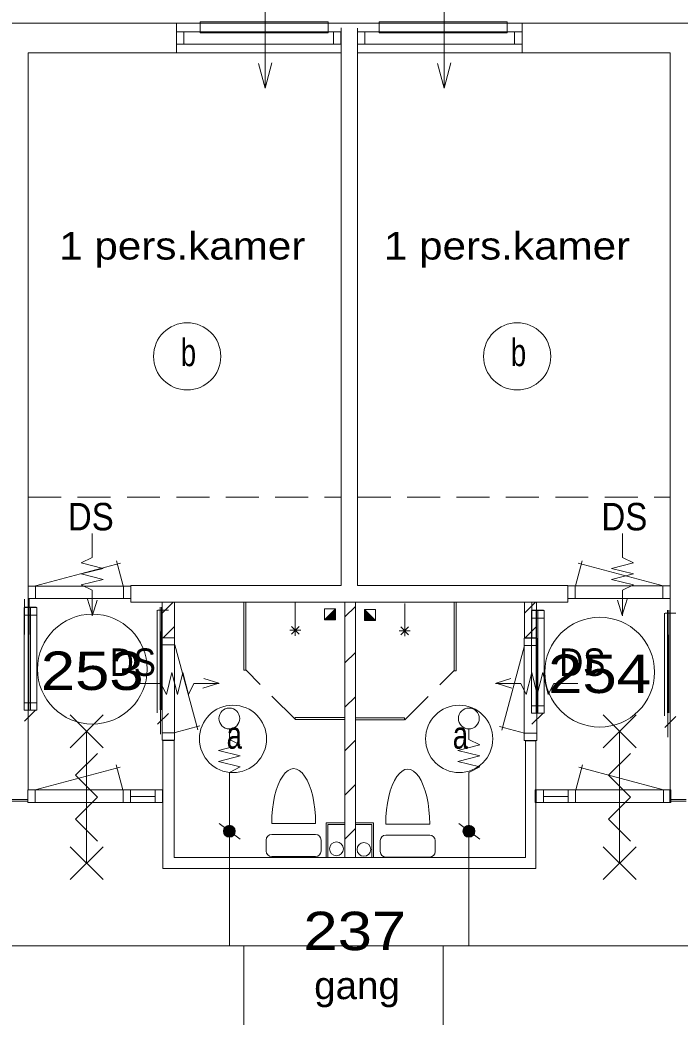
# Model space of a CAD drawing. Extents: x 295824 to 414724, y 24924 to 109024.
# Drawn here: x 314015 to 320029, y 95369 to 104447 of the extents above; entities that cross this region are included whole.
import ezdxf
from ezdxf.enums import TextEntityAlignment as Align

# ---------------------------------------------------------------- set-up
doc = ezdxf.new("R2010")
doc.units = 0
doc.header["$LTSCALE"] = 100
doc.linetypes.add('MEDIUM_DASHED', pattern=[4.5, 3, -1.5])
for name, color, linetype, lineweight in [('1', 7, 'Continuous', 13), ('16', 7, 'Continuous', 13), ('24', 7, 'Continuous', 13), ('61', 7, 'Continuous', 13)]:
    doc.layers.add(name, color=color, linetype=linetype, lineweight=lineweight)

msp = doc.modelspace()

# ---------------------------------------------------------------- hatches: boundary and pattern name
at = {"layer": '24'}
for points in [[(315977.2, 97060.5, 1), (315868.6, 97060.5, 1)], [(318159.2, 97060.5, 1), (318050.6, 97060.5, 1)]]:
    msp.add_hatch(color=256, dxfattribs=at).paths.add_polyline_path(points)
at = {"layer": '61'}
for points in [[(316790.6, 98985.1), (316890.6, 99085.1), (316890.6, 98985.1)], [(317253, 98979.7), (317153, 99079.7), (317153, 98979.7)]]:
    msp.add_hatch(color=256, dxfattribs=at).paths.add_polyline_path(points)

# ---------------------------------------------------------------- linework, layer by layer
at = {"layer": '1'}
for p, q in [((315922.9, 97029.2), (315922.9, 96018.7)), ((318104.9, 97022.5), (318104.9, 96018.7)), ((316056.2, 95135.8), (316056.2, 96018.7)), ((317871.7, 95130.8), (317871.7, 96018.7))]:
    msp.add_line(p, q, dxfattribs=at)
at = {"layer": '16'}
for p, q in [((314573.7, 99404.1), (314773.7, 99454.1)), ((319604, 99404.1), (319404, 99454.1)), ((315450.2, 98305.9), (315400.2, 98505.9)), ((318727.6, 98305.9), (318777.6, 98505.9))]:
    msp.add_line(p, q, dxfattribs=at)
at = {"layer": '24'}
for p, q in [((316247.7, 103826.9), (316188.1, 104049.3)), ((317880, 103826.9), (317820.5, 104049.3)), ((314677.1, 99028.7), (314632.1, 99172.8)), ((314719.5, 99164.5), (314677.1, 99028.7)), ((319458.2, 99164.5), (319500.7, 99028.7)), ((319500.7, 99028.7), (319545.7, 99172.8)), ((315825.6, 98409.3), (315681.4, 98364.2)), ((315689.8, 98451.7), (315825.6, 98409.3)), ((318488, 98451.7), (318352.2, 98409.3)), ((318352.2, 98409.3), (318496.4, 98364.2)), ((315922.9, 97545.9), (315922.9, 97006.4)), ((318104.9, 97545.9), (318104.9, 97037.5)), ((315831.3, 97131.3), (316022.9, 96989.6)), ((318013.3, 97131.3), (318204.8, 96989.6)), ((304113.6, 96018.7), (328710.3, 96018.7))]:
    msp.add_line(p, q, dxfattribs=at)
for points in [[(316247.7, 104801.9), (316247.7, 103826.9), (316309.4, 104057.1)], [(317880, 104801.9), (317880, 103826.9), (317941.7, 104057.1)], [(314773.7, 99454.1), (314573.7, 99504.1), (314673.7, 99554.1), (314673.7, 99772.8)], [(319404, 99454.1), (319604, 99504.1), (319504, 99554.1), (319504, 99772.8)], [(314673.7, 99022.8), (314673.7, 99254.1), (314573.7, 99304.1), (314773.7, 99354.1), (314573.7, 99404.1)], [(319504, 99022.8), (319504, 99254.1), (319604, 99304.1), (319404, 99354.1), (319604, 99404.1)], [(315400.2, 98505.9), (315350.2, 98305.9), (315300.2, 98405.9), (315081.4, 98405.9)], [(315831.4, 98405.9), (315600.2, 98405.9), (315550.2, 98305.9), (315500.2, 98505.9), (315450.2, 98305.9)], [(318346.4, 98405.9), (318577.6, 98405.9), (318627.6, 98305.9), (318677.6, 98505.9), (318727.6, 98305.9)], [(318777.6, 98505.9), (318827.6, 98305.9), (318877.6, 98405.9), (319096.4, 98405.9)], [(315922.9, 97995.9), (315922.9, 97895.9), (316022.9, 97845.9), (315822.9, 97795.9), (316022.9, 97745.9), (315822.9, 97695.9), (316022.9, 97645.9), (315922.9, 97595.9), (315922.9, 97545.9)], [(318104.9, 97995.9), (318104.9, 97895.9), (318204.9, 97845.9), (318004.9, 97795.9), (318204.9, 97745.9), (318004.9, 97695.9), (318204.9, 97645.9), (318104.9, 97595.9), (318104.9, 97545.9)]]:
    msp.add_lwpolyline(points, dxfattribs=at)
for points in [[(315656.4, 104331), (316822.4, 104331), (316822.4, 104431), (315656.4, 104431)], [(317288.7, 104331), (318454.7, 104331), (318454.7, 104431), (317288.7, 104431)]]:
    msp.add_lwpolyline(points, close=True, dxfattribs=at)
for centre, radius in [((315922.9, 98087.5), 95), ((318104.9, 98087.5), 95), ((315922.9, 97060.5), 54.3), ((318104.9, 97060.5), 54.3)]:
    msp.add_circle(centre, radius, dxfattribs=at)
at = {"layer": '61'}
for p, q in [((315441, 104147.6), (315441, 104417.6)), ((318589.5, 104147.6), (318589.5, 104417.6)), ((315508.1, 104225.9), (315508.1, 104339.8)), ((316873.1, 104225.3), (316873.1, 104339.3)), ((316940.1, 104375), (316940.1, 99297.6)), ((317090.1, 104371.2), (317090.1, 99297.6)), ((317156.6, 104226.2), (317156.6, 104340.2)), ((318520.9, 104225.9), (318520.9, 104339.6)), ((314090.1, 104147.6), (316940.1, 104147.6)), ((314090.1, 97436.7), (314090.1, 104147.6)), ((319940.1, 104147.6), (317090.1, 104147.6)), ((319940.1, 97436.7), (319940.1, 104147.6)), ((314157.5, 99293.7), (314930.2, 99500.7)), ((314955.9, 99294.3), (314895.1, 99521.1)), ((319075.3, 99295.4), (319136, 99522.2)), ((319873.7, 99294.8), (319101, 99501.8)), ((314158.2, 99179), (314158.2, 99293)), ((314958.2, 99179), (314958.2, 99293)), ((315025.2, 99179), (315025.2, 99293)), ((319005.9, 99180.1), (319005.9, 99294.1)), ((319072.9, 99180.1), (319072.9, 99294.1)), ((319872.9, 99180.1), (319872.9, 99294.1)), ((314056.5, 98850.8), (314056.5, 99174.9)), ((314099.2, 98850.8), (314099.2, 99174.9)), ((315310.4, 99046.8), (315410.1, 99146.5)), ((315311.9, 98823), (315311.9, 99147)), ((315311.9, 99147), (315421.9, 99147)), ((315421.9, 98823), (315421.9, 99147)), ((316073.1, 99147.4), (316073.1, 98526.9)), ((316523, 98940.9), (316523, 99140.9)), ((316975, 99147.6), (316975, 96822.6)), ((317071.3, 99147.6), (317071.3, 96822.6)), ((317520.7, 98935.5), (317520.7, 99135.5)), ((317970.5, 99142), (317970.5, 98521.5)), ((318610.9, 98823), (318610.9, 99147)), ((318610.9, 99147), (318720.8, 99147)), ((318612.6, 99046.8), (318712.3, 99146.5)), ((318678.1, 98823), (318678.1, 99147)), ((318720.8, 98823), (318720.8, 99147)), ((314163.1, 99100), (314057.9, 99100)), ((314096.6, 98163.9), (314096.6, 99096.4)), ((314112.5, 98163.9), (314112.5, 99096.4)), ((314169.1, 98163.9), (314169.1, 99096.4)), ((315264.9, 98138.7), (315264.9, 99072.7)), ((315367.2, 99073.5), (315272.4, 99073.5)), ((315293.7, 98166.6), (315293.7, 99100.6)), ((315304.8, 98166.6), (315304.8, 99100.6)), ((316975.5, 99011.5), (317071.3, 99107.3)), ((318784.8, 99072.1), (318679.5, 99072.1)), ((318718.2, 98136.1), (318718.2, 99068.5)), ((318734.1, 98136.1), (318734.1, 99068.5)), ((318790.7, 98136.1), (318790.7, 99068.5)), ((319886.5, 98110.9), (319886.5, 99044.9)), ((319988.8, 99045.7), (319894, 99045.7)), ((319915.4, 98138.8), (319915.4, 99072.8)), ((319926.4, 98138.8), (319926.4, 99072.8)), ((314169.1, 99029.4), (314055.1, 99029.4)), ((318790.7, 99001.5), (318676.7, 99001.5)), ((315295.2, 98877.8), (315295.2, 97945.4)), ((315322.7, 98824.2), (315422.4, 98923.9)), ((316573, 98890.9), (316473, 98890.9)), ((316558.4, 98926.2), (316487.6, 98855.5)), ((316558.4, 98855.5), (316487.6, 98926.2)), ((316523, 98940.9), (316523, 98840.9)), ((317470.7, 98885.5), (317570.7, 98885.5)), ((317485.3, 98920.9), (317556.1, 98850.2)), ((317485.3, 98850.2), (317556.1, 98920.9)), ((317520.7, 98935.5), (317520.7, 98835.5)), ((318621.2, 98824.2), (318720.9, 98923.9)), ((315310.1, 98822.1), (315310.1, 97889.7)), ((315311.9, 98823), (315421.9, 98823)), ((318610.2, 98819.4), (318724.2, 98819.4)), ((318610.9, 98823), (318720.8, 98823)), ((318723.6, 98819.4), (318723.6, 97885.4)), ((319916.9, 98850), (319916.9, 97917.6)), ((315310.1, 98756.7), (315424.1, 98756.7)), ((315427.3, 98757.4), (315634.3, 97984.7)), ((316975.5, 98593.4), (317071.3, 98689.2)), ((318611.5, 98753.2), (318404.5, 97980.5)), ((318723.6, 98752.4), (318609.6, 98752.4)), ((314169.1, 98229.4), (314055.1, 98229.4)), ((316975.5, 98188.8), (317071.3, 98284.6)), ((314156.5, 98161.9), (314056.8, 98062.2)), ((314167.3, 98163.1), (314057.3, 98163.1)), ((315367.3, 98134), (315267.6, 98034.3)), ((318790.7, 98201.5), (318676.7, 98201.5)), ((318778.1, 98134), (318678.4, 98034.3)), ((318788.9, 98135.2), (318679, 98135.2)), ((314772.1, 98119.9), (314472.1, 97819.9)), ((314472.1, 98119.9), (314772.1, 97819.9)), ((316973.2, 98097.4), (316524, 98097.4)), ((316524, 98079.4), (316524, 98097.4)), ((316973.5, 98079.4), (316524, 98079.4)), ((317070.2, 98074), (317519.7, 98074)), ((317070.5, 98092), (317519.7, 98092)), ((317519.7, 98074), (317519.7, 98092)), ((319628, 98119.9), (319328, 97819.9)), ((319328, 98119.9), (319628, 97819.9)), ((319988.9, 98106.1), (319889.2, 98006.4)), ((314622.1, 96769.9), (314622.1, 97969.9)), ((315310.1, 97956.7), (315424.1, 97956.7)), ((315427.9, 97959), (315654.8, 98019.8)), ((318610.9, 97954.8), (318384, 98015.6)), ((318723.6, 97952.4), (318609.6, 97952.4)), ((319478, 96769.9), (319478, 97969.9)), ((315316.1, 97886.1), (315316.1, 97320.2)), ((315316.1, 97886.1), (315421.3, 97886.1)), ((316975.5, 97792.8), (317071.3, 97888.6)), ((318621.3, 97884.6), (318621.3, 96822.6)), ((318621.3, 97884.6), (318716.1, 97884.6)), ((318716.1, 97884.6), (318716.1, 97422.6)), ((314154.1, 97437.3), (314926.9, 97644.4)), ((314952.5, 97437.9), (314891.8, 97664.8)), ((319079.9, 97437.9), (319140.6, 97664.8)), ((319878.3, 97437.3), (319105.5, 97644.4)), ((314154.9, 97322.7), (314154.9, 97436.7)), ((314954.9, 97322.7), (314954.9, 97436.7)), ((315021.9, 97322.7), (315021.9, 97436.7)), ((315247.9, 97322.7), (315247.9, 97436.7)), ((316975.5, 97389.4), (317071.3, 97485.2)), ((318784.5, 97322.7), (318784.5, 97436.7)), ((319010.5, 97322.7), (319010.5, 97436.7)), ((319077.5, 97322.7), (319077.5, 97436.7)), ((319877.5, 97322.7), (319877.5, 97436.7)), ((313944.8, 97348.9), (314086, 97348.9)), ((313944.8, 97333.9), (314086, 97333.9)), ((315247.9, 97376.8), (315021.9, 97376.8)), ((318784.5, 97376.8), (319010.5, 97376.8)), ((319943.6, 97348.9), (320084.8, 97348.9)), ((319943.6, 97333.9), (320084.8, 97333.9)), ((316708.7, 97130.5), (316308.7, 97130.5)), ((316821.2, 97123.1), (316971.2, 97123.1)), ((316821.2, 96823.1), (316821.2, 97123.1)), ((316975.5, 96988.5), (317071.3, 97084.3)), ((317071.3, 97122.6), (317221.3, 97122.6)), ((317221.3, 97122.6), (317221.3, 96822.6)), ((317748.1, 97125.6), (317348.1, 97125.6)), ((316258.7, 96880.5), (316258.7, 96980.5)), ((316308.7, 97030.5), (316708.7, 97030.5)), ((316758.7, 96980.5), (316758.7, 96880.5)), ((317298.1, 96875.6), (317298.1, 96975.6)), ((317348.1, 97025.6), (317748.1, 97025.6)), ((317798.1, 96975.6), (317798.1, 96875.6)), ((314772.1, 96919.9), (314472.1, 96619.9)), ((314472.1, 96919.9), (314772.1, 96619.9)), ((319628, 96919.9), (319328, 96619.9)), ((319328, 96919.9), (319628, 96619.9)), ((316708.7, 96830.5), (316308.7, 96830.5)), ((317748.1, 96825.6), (317348.1, 96825.6))]:
    msp.add_line(p, q, dxfattribs=at)
at = {"layer": '61', "linetype": 'MEDIUM_DASHED'}
for p, q in [((314090.7, 100101), (316939.8, 100101)), ((317093.1, 100101), (319940.1, 100101)), ((316522, 98079.8), (316075.1, 98526.7)), ((317521.7, 98074.4), (317968.6, 98521.3))]:
    msp.add_line(p, q, dxfattribs=at)
at = {"layer": '61'}
for points in [[(301796.6, 92184.5), (301820.1, 104417.6), (332210.1, 104417.6)], [(314091.2, 99179), (314091.2, 99293), (315025.2, 99293)], [(315025.2, 99179), (314091.2, 99179), (314091.2, 99293)], [(316941.1, 99297.6), (315026, 99297.6), (315026, 99147.6), (319005.4, 99147.6)], [(317091.1, 99297.6), (319005.4, 99297.6), (319005.4, 99147.6)], [(319939.9, 99180.1), (319939.9, 99294.1), (319005.9, 99294.1)], [(319005.9, 99180.1), (319939.9, 99180.1), (319939.9, 99294.1)], [(316055.1, 99147.4), (316055.1, 98526.9), (316073.1, 98526.9)], [(317988.5, 99142), (317988.5, 98521.5), (317970.5, 98521.5)], [(316890.6, 99085.1), (316890.6, 98985.1), (316790.6, 98985.1)], [(317153, 99079.7), (317153, 98979.7), (317253, 98979.7)], [(315421.3, 97886.1), (315421.3, 96822.6), (318621.3, 96822.6)], [(314722.1, 96969.9), (314522.1, 97169.9), (314722.1, 97369.9), (314522.1, 97569.9), (314722.1, 97769.9)], [(319578, 96969.9), (319378, 97169.9), (319578, 97369.9), (319378, 97569.9), (319578, 97769.9)], [(315316.1, 97322.6), (315316.1, 96722.6), (318716.1, 96722.6), (318716.1, 97322.6)], [(316806.2, 96823.1), (316806.2, 97138.1), (316971.2, 97138.1)], [(317071.3, 97137.6), (317236.3, 97137.6), (317236.3, 96822.6)]]:
    msp.add_lwpolyline(points, dxfattribs=at)
for points in [[(315441.2, 104225.8), (315441.2, 104339.8), (316939.9, 104339.8), (316939.9, 104225.8)], [(317090.2, 104225.9), (317090.2, 104339.9), (318589.6, 104339.9), (318589.6, 104225.9)], [(314169.1, 99097.3), (314055.1, 99097.3), (314055.1, 98163.3), (314169.1, 98163.3)], [(316890.6, 99085.1), (316790.6, 99085.1), (316790.6, 98985.1)], [(316790.6, 98985.1), (316890.6, 99085.1), (316890.6, 98985.1)], [(317153, 99079.7), (317253, 99079.7), (317253, 98979.7)], [(317253, 98979.7), (317153, 99079.7), (317153, 98979.7)], [(318790.7, 99069.4), (318676.7, 99069.4), (318676.7, 98135.4), (318790.7, 98135.4)], [(315310.1, 97888.7), (315424.1, 97888.7), (315424.1, 98822.7), (315310.1, 98822.7)], [(318723.6, 98819.4), (318723.6, 97885.4), (318609.6, 97885.4), (318609.6, 98819.4)], [(314087.9, 97322.7), (314087.9, 97436.7), (315314.2, 97436.7), (315314.2, 97322.7)], [(314087.9, 97322.7), (314087.9, 97436.7), (315314.2, 97436.7), (315314.2, 97322.7)], [(318709.2, 97322.7), (318709.2, 97436.7), (319936.2, 97436.7), (319936.2, 97322.7)], [(318717.5, 97322.7), (318717.5, 97436.7), (319944.5, 97436.7), (319944.5, 97322.7)]]:
    msp.add_lwpolyline(points, close=True, dxfattribs=at)
for centre, radius in [((315538.5, 101384.2), 306.3), ((318545.3, 101384.2), 306.3), ((314675.2, 98536.8), 500), ((319296.8, 98509), 500), ((315956.1, 97901.5), 306.3), ((318016.4, 97901.5), 306.3), ((316898.8, 96900.6), 62.5), ((317148.8, 96895), 62.5)]:
    msp.add_circle(centre, radius, dxfattribs=at)
for centre, start, end in [((316308.7, 96980.5), 90, 180), ((316708.7, 96980.5), 0, 90), ((317348.1, 96975.6), 90, 180), ((317748.1, 96975.6), 0, 90), ((316308.7, 96880.5), 180, 270), ((316708.7, 96880.5), 270, 0), ((317348.1, 96875.6), 180, 270), ((317748.1, 96875.6), 270, 0)]:
    msp.add_arc(centre, 50, start, end, dxfattribs=at)
for centre in [(316508.7, 97130.5), (317548.1, 97125.6)]:
    msp.add_ellipse(centre, major_axis=(0, 500), ratio=0.4, start_param=4.712389, end_param=7.853982, dxfattribs=at)

# ---------------------------------------------------------------- texts
at = {"layer": '24', "width": 0.9}
for p in [(314451.9, 99799.9), (319312.5, 99799.9), (314835, 98474.9), (318929.4, 98474.9)]:
    msp.add_text('DS', height=250, dxfattribs=at).set_placement(p)
at = {"layer": '61'}
for s, height, width, p in [('1 pers.kamer', 250, 1.15, (314372.5, 102265.6)), ('1 pers.kamer', 250, 1.15, (317330.9, 102265.6)), ('b', 250, 0.75, (315480.5, 101295)), ('b', 250, 0.75, (318487.3, 101295)), ('a', 250, 0.75, (315898.1, 97812.3)), ('a', 250, 0.75, (317958.4, 97812.3)), ('237', 350, 1.2, (316597.2, 95978.1)), ('gang', 250, 1.05, (316695.7, 95532.1))]:
    msp.add_text(s, height=height, dxfattribs=dict(at, width=width)).set_placement(p)
at = {"layer": '61', "width": 1.2}
for s, p in [('253', (314673.7, 98346.9)), ('254', (319295.3, 98319.1))]:
    msp.add_text(s, height=350, dxfattribs=at).set_placement(p, align=Align.CENTER)

doc.saveas('drawing.dxf')
